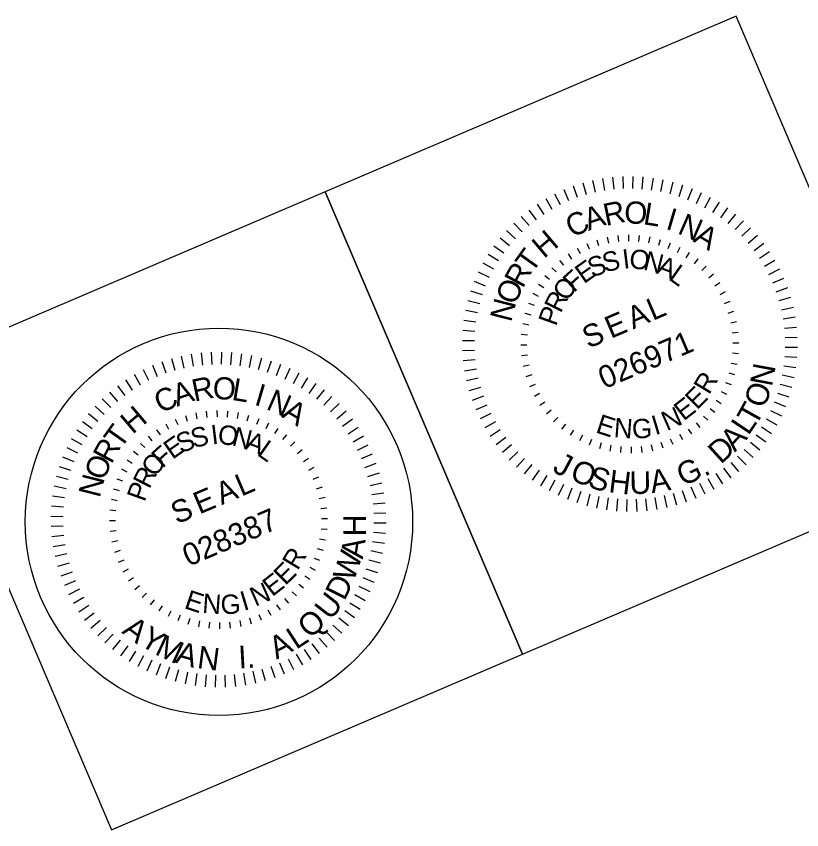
# Model space of a CAD drawing. Extents: x 1882804 to 2194450, y 87424 to 845437.
# Drawn here: x 2194137 to 2194312.8, y 87438 to 87620.1 of the extents above; entities that cross this region are included whole.
import ezdxf

# ---------------------------------------------------------------- set-up
doc = ezdxf.new("R2010")
doc.units = 0
doc.layers.add('Scratch_Level_1', color=7, linetype='Continuous')
doc.layers.add('Sheet Title CELL', color=7, linetype='Continuous')

msp = doc.modelspace()

# ---------------------------------------------------------------- linework, layer by layer
at = {"layer": 'Scratch_Level_1'}
for points in [[(2194250.33, 87477.33), (2194342.29, 87516.6), (2194298.12, 87620.06), (2194206.15, 87580.8)], [(2194158.31, 87438.05), (2194250.33, 87477.33), (2194206.15, 87580.8), (2194114.14, 87541.51)]]:
    msp.add_lwpolyline(points, close=True, dxfattribs=at)
msp.add_circle((2194182.37, 87506.94), 43.34, dxfattribs=at)
msp.add_circle((2194182.37, 87506.94), 43.34, dxfattribs=at)
at = {"layer": 'Sheet Title CELL'}
for p, q in [((2194266.67, 87580.67), (2194266.07, 87583.31)), ((2194268.73, 87581.07), (2194268.29, 87583.74)), ((2194270.81, 87581.34), (2194270.54, 87584.04)), ((2194272.91, 87581.49), (2194272.8, 87584.2)), ((2194275.01, 87581.52), (2194275.06, 87584.23)), ((2194277.11, 87581.41), (2194277.33, 87584.11)), ((2194279.2, 87581.18), (2194279.58, 87583.87)), ((2194281.27, 87580.83), (2194281.81, 87583.48)), ((2194260.67, 87578.73), (2194259.61, 87581.22)), ((2194262.63, 87579.5), (2194261.72, 87582.05)), ((2194264.63, 87580.14), (2194263.88, 87582.75)), ((2194283.32, 87580.35), (2194284.02, 87582.96)), ((2194285.33, 87579.74), (2194286.19, 87582.31)), ((2194287.3, 87579.02), (2194288.31, 87581.53)), ((2194258.77, 87577.85), (2194257.56, 87580.27)), ((2194289.23, 87578.17), (2194290.39, 87580.63)), ((2194291.1, 87577.22), (2194292.41, 87579.6)), ((2194255.13, 87575.74), (2194253.64, 87578)), ((2194256.92, 87576.85), (2194255.56, 87579.2)), ((2194292.91, 87576.15), (2194294.36, 87578.44)), ((2194253.42, 87574.53), (2194251.79, 87576.7)), ((2194294.65, 87574.98), (2194296.23, 87577.18)), ((2194296.32, 87573.7), (2194298.03, 87575.8)), ((2194251.78, 87573.22), (2194250.02, 87575.28)), ((2194297.91, 87572.32), (2194299.74, 87574.32)), ((2194248.75, 87570.3), (2194246.75, 87572.14)), ((2194250.22, 87571.81), (2194248.34, 87573.76)), ((2194299.41, 87570.85), (2194301.36, 87572.73)), ((2194247.37, 87568.72), (2194245.27, 87570.43)), ((2194269.6, 87569.28), (2194269.32, 87570.61)), ((2194271.83, 87569.64), (2194271.68, 87570.99)), ((2194274.09, 87569.77), (2194274.07, 87571.13)), ((2194276.35, 87569.69), (2194276.46, 87571.04)), ((2194278.59, 87569.38), (2194278.84, 87570.71)), ((2194300.82, 87569.29), (2194302.88, 87571.05)), ((2194246.09, 87567.05), (2194243.89, 87568.63)), ((2194265.29, 87567.93), (2194264.76, 87569.17)), ((2194267.41, 87568.71), (2194267, 87570)), ((2194280.79, 87568.85), (2194281.17, 87570.15)), ((2194282.92, 87568.12), (2194283.43, 87569.37)), ((2194302.13, 87567.66), (2194304.3, 87569.29)), ((2194244.92, 87565.31), (2194242.63, 87566.75)), ((2194261.33, 87565.75), (2194260.56, 87566.87)), ((2194263.25, 87566.94), (2194262.6, 87568.13)), ((2194284.98, 87567.17), (2194285.6, 87568.37)), ((2194286.93, 87566.03), (2194287.67, 87567.17)), ((2194303.34, 87565.94), (2194305.61, 87567.43)), ((2194259.53, 87564.39), (2194258.66, 87565.42)), ((2194288.76, 87564.7), (2194289.61, 87565.76)), ((2194304.45, 87564.15), (2194306.8, 87565.51)), ((2194243.85, 87563.5), (2194241.48, 87564.8)), ((2194257.87, 87562.85), (2194256.9, 87563.8)), ((2194290.45, 87563.2), (2194291.4, 87564.17)), ((2194305.45, 87562.3), (2194307.87, 87563.52)), ((2194242.89, 87561.63), (2194240.44, 87562.78)), ((2194256.37, 87561.16), (2194255.31, 87562.01)), ((2194291.99, 87561.54), (2194293.03, 87562.41)), ((2194306.33, 87560.39), (2194308.82, 87561.46)), ((2194242.05, 87559.7), (2194239.54, 87560.71)), ((2194255.04, 87559.33), (2194253.91, 87560.07)), ((2194293.36, 87559.74), (2194294.48, 87560.51)), ((2194241.33, 87557.72), (2194238.76, 87558.58)), ((2194253.9, 87557.37), (2194252.7, 87558)), ((2194294.54, 87557.82), (2194295.73, 87558.47)), ((2194307.1, 87558.44), (2194309.65, 87559.35)), ((2194240.73, 87555.71), (2194238.1, 87556.41)), ((2194252.95, 87555.32), (2194251.7, 87555.83)), ((2194295.53, 87555.78), (2194296.77, 87556.31)), ((2194307.74, 87556.44), (2194310.35, 87557.19)), ((2194240.24, 87553.67), (2194237.59, 87554.21)), ((2194296.31, 87553.66), (2194297.61, 87554.07)), ((2194308.27, 87554.4), (2194310.92, 87555)), ((2194252.22, 87553.19), (2194250.91, 87553.56)), ((2194308.67, 87552.34), (2194311.35, 87552.78)), ((2194239.89, 87551.6), (2194237.2, 87551.97)), ((2194251.69, 87550.98), (2194250.36, 87551.23)), ((2194296.89, 87551.47), (2194298.21, 87551.75)), ((2194308.95, 87550.26), (2194311.64, 87550.53)), ((2194239.66, 87549.51), (2194236.95, 87549.72)), ((2194251.38, 87548.74), (2194250.03, 87548.86)), ((2194297.24, 87549.24), (2194298.59, 87549.39)), ((2194239.55, 87547.41), (2194236.84, 87547.46)), ((2194297.38, 87546.98), (2194298.73, 87547)), ((2194309.1, 87548.16), (2194311.8, 87548.27)), ((2194180.83, 87542.18), (2194180.72, 87544.89)), ((2194182.93, 87542.2), (2194182.98, 87544.91)), ((2194185.03, 87542.1), (2194185.24, 87544.8)), ((2194239.58, 87545.31), (2194236.87, 87545.2)), ((2194251.3, 87546.48), (2194249.94, 87546.47)), ((2194309.12, 87546.06), (2194311.83, 87546.01)), ((2194172.55, 87540.83), (2194171.8, 87543.43)), ((2194174.59, 87541.35), (2194173.99, 87544)), ((2194176.65, 87541.75), (2194176.21, 87544.43)), ((2194178.73, 87542.03), (2194178.46, 87544.73)), ((2194187.12, 87541.87), (2194187.5, 87544.55)), ((2194189.19, 87541.51), (2194189.73, 87544.17)), ((2194191.23, 87541.03), (2194191.93, 87543.65)), ((2194193.25, 87540.43), (2194194.1, 87543)), ((2194239.73, 87543.21), (2194237.03, 87542.94)), ((2194251.43, 87544.23), (2194250.08, 87544.08)), ((2194297.29, 87544.73), (2194298.64, 87544.61)), ((2194309.02, 87543.96), (2194311.72, 87543.75)), ((2194168.59, 87539.41), (2194167.53, 87541.91)), ((2194170.55, 87540.18), (2194169.64, 87542.73)), ((2194195.22, 87539.7), (2194196.23, 87542.22)), ((2194197.15, 87538.86), (2194198.31, 87541.31)), ((2194251.79, 87541.99), (2194250.46, 87541.71)), ((2194296.98, 87542.48), (2194298.32, 87542.23)), ((2194308.79, 87541.87), (2194311.47, 87541.49)), ((2194164.84, 87537.54), (2194163.48, 87539.88)), ((2194166.69, 87538.53), (2194165.47, 87540.96)), ((2194199.02, 87537.9), (2194200.33, 87540.28)), ((2194240, 87541.13), (2194237.33, 87540.69)), ((2194252.36, 87539.81), (2194251.07, 87539.4)), ((2194296.46, 87540.29), (2194297.76, 87539.9)), ((2194308.43, 87539.8), (2194311.08, 87539.26)), ((2194163.05, 87536.43), (2194161.55, 87538.69)), ((2194200.83, 87536.84), (2194202.27, 87539.13)), ((2194202.57, 87535.66), (2194204.15, 87537.86)), ((2194240.4, 87539.06), (2194237.76, 87538.47)), ((2194253.14, 87537.69), (2194251.9, 87537.15)), ((2194295.72, 87538.15), (2194296.98, 87537.64)), ((2194307.95, 87537.76), (2194310.57, 87537.06)), ((2194159.7, 87533.9), (2194157.94, 87535.96)), ((2194161.34, 87535.22), (2194159.7, 87537.38)), ((2194204.24, 87534.38), (2194205.95, 87536.49)), ((2194240.93, 87537.03), (2194238.32, 87536.27)), ((2194294.78, 87536.09), (2194295.98, 87535.47)), ((2194307.34, 87535.74), (2194309.92, 87534.89)), ((2194158.14, 87532.49), (2194156.26, 87534.44)), ((2194205.83, 87533.01), (2194207.66, 87535)), ((2194241.58, 87535.03), (2194239.02, 87534.12)), ((2194254.13, 87535.65), (2194252.95, 87535)), ((2194293.63, 87534.14), (2194294.77, 87533.4)), ((2194156.67, 87530.99), (2194154.67, 87532.83)), ((2194207.33, 87531.54), (2194209.28, 87533.42)), ((2194242.34, 87533.07), (2194239.85, 87532.01)), ((2194255.32, 87533.72), (2194254.2, 87532.96)), ((2194292.31, 87532.31), (2194293.36, 87531.46)), ((2194306.62, 87533.77), (2194309.13, 87532.76)), ((2194155.29, 87529.4), (2194153.19, 87531.11)), ((2194175.33, 87529.4), (2194174.92, 87530.69)), ((2194177.51, 87529.97), (2194177.24, 87531.3)), ((2194179.75, 87530.32), (2194179.6, 87531.67)), ((2194182.01, 87530.46), (2194181.99, 87531.82)), ((2194184.27, 87530.37), (2194184.38, 87531.73)), ((2194186.51, 87530.07), (2194186.76, 87531.4)), ((2194188.71, 87529.54), (2194189.08, 87530.84)), ((2194208.74, 87529.98), (2194210.8, 87531.74)), ((2194243.23, 87531.17), (2194240.8, 87529.95)), ((2194256.69, 87531.92), (2194255.64, 87531.05)), ((2194258.22, 87530.27), (2194257.27, 87529.3)), ((2194290.81, 87530.62), (2194291.77, 87529.67)), ((2194305.78, 87531.85), (2194308.23, 87530.69)), ((2194154.01, 87527.73), (2194151.81, 87529.32)), ((2194171.17, 87527.62), (2194170.52, 87528.81)), ((2194173.21, 87528.61), (2194172.67, 87529.86)), ((2194190.84, 87528.8), (2194191.35, 87530.06)), ((2194192.9, 87527.86), (2194193.52, 87529.06)), ((2194210.05, 87528.34), (2194212.22, 87529.97)), ((2194244.22, 87529.32), (2194241.87, 87527.96)), ((2194259.91, 87528.77), (2194259.06, 87527.71)), ((2194289.15, 87529.08), (2194290.02, 87528.04)), ((2194304.82, 87529.97), (2194307.2, 87528.67)), ((2194152.84, 87525.99), (2194150.55, 87527.44)), ((2194169.25, 87526.44), (2194168.48, 87527.56)), ((2194194.85, 87526.72), (2194195.59, 87527.85)), ((2194211.26, 87526.62), (2194213.53, 87528.12)), ((2194245.33, 87527.53), (2194243.07, 87526.03)), ((2194261.74, 87527.44), (2194261, 87526.3)), ((2194287.34, 87527.71), (2194288.11, 87526.6)), ((2194303.75, 87528.16), (2194306.05, 87526.72)), ((2194151.77, 87524.18), (2194149.39, 87525.49)), ((2194167.45, 87525.07), (2194166.57, 87526.11)), ((2194196.68, 87525.39), (2194197.53, 87526.44)), ((2194198.37, 87523.89), (2194199.32, 87524.86)), ((2194212.37, 87524.84), (2194214.72, 87526.19)), ((2194246.54, 87525.81), (2194244.37, 87524.18)), ((2194263.7, 87526.3), (2194263.07, 87525.09)), ((2194265.75, 87525.35), (2194265.25, 87524.09)), ((2194283.38, 87525.54), (2194283.92, 87524.3)), ((2194285.42, 87526.53), (2194286.07, 87525.34)), ((2194302.58, 87526.42), (2194304.78, 87524.84)), ((2194150.81, 87522.31), (2194148.36, 87523.47)), ((2194165.79, 87523.54), (2194164.82, 87524.48)), ((2194199.91, 87522.23), (2194200.95, 87523.1)), ((2194213.37, 87522.99), (2194215.79, 87524.2)), ((2194247.85, 87524.17), (2194245.79, 87522.42)), ((2194267.89, 87524.61), (2194267.51, 87523.31)), ((2194270.09, 87524.09), (2194269.84, 87522.75)), ((2194272.33, 87523.78), (2194272.21, 87522.43)), ((2194274.59, 87523.69), (2194274.6, 87522.34)), ((2194276.84, 87523.83), (2194276.99, 87522.48)), ((2194279.08, 87524.18), (2194279.36, 87522.86)), ((2194281.26, 87524.76), (2194281.67, 87523.47)), ((2194299.93, 87523.16), (2194301.92, 87521.33)), ((2194301.3, 87524.75), (2194303.4, 87523.04)), ((2194149.97, 87520.38), (2194147.46, 87521.39)), ((2194164.29, 87521.84), (2194163.23, 87522.69)), ((2194201.28, 87520.43), (2194202.39, 87521.19)), ((2194214.25, 87521.08), (2194216.74, 87522.14)), ((2194249.27, 87522.62), (2194247.31, 87520.74)), ((2194250.77, 87521.14), (2194248.93, 87519.15)), ((2194298.45, 87521.66), (2194300.34, 87519.71)), ((2194162.96, 87520.01), (2194161.82, 87520.75)), ((2194215.02, 87519.12), (2194217.57, 87520.04)), ((2194252.35, 87519.77), (2194250.64, 87517.67)), ((2194296.9, 87520.25), (2194298.66, 87518.19)), ((2194149.25, 87518.41), (2194146.68, 87519.27)), ((2194161.82, 87518.06), (2194160.62, 87518.69)), ((2194202.46, 87518.5), (2194203.65, 87519.15)), ((2194215.66, 87517.12), (2194218.27, 87517.88)), ((2194254.02, 87518.49), (2194252.44, 87516.29)), ((2194293.54, 87517.73), (2194295.04, 87515.47)), ((2194295.26, 87518.94), (2194296.89, 87516.77)), ((2194148.64, 87516.4), (2194146.02, 87517.1)), ((2194160.87, 87516.01), (2194159.62, 87516.51)), ((2194203.45, 87516.47), (2194204.69, 87517)), ((2194216.19, 87515.09), (2194218.83, 87515.69)), ((2194255.76, 87517.32), (2194254.32, 87515.02)), ((2194257.57, 87516.25), (2194256.27, 87513.87)), ((2194291.75, 87516.62), (2194293.11, 87514.27)), ((2194148.16, 87514.35), (2194145.51, 87514.89)), ((2194160.13, 87513.87), (2194158.83, 87514.25)), ((2194204.23, 87514.35), (2194205.52, 87514.76)), ((2194259.45, 87515.29), (2194258.29, 87512.84)), ((2194261.37, 87514.45), (2194260.36, 87511.93)), ((2194286.04, 87513.97), (2194286.95, 87511.42)), ((2194288, 87514.74), (2194289.06, 87512.25)), ((2194289.9, 87515.62), (2194291.12, 87513.2)), ((2194147.81, 87512.28), (2194145.12, 87512.66)), ((2194204.81, 87512.16), (2194206.13, 87512.44)), ((2194216.59, 87513.03), (2194219.27, 87513.46)), ((2194263.34, 87513.73), (2194262.49, 87511.16)), ((2194265.36, 87513.12), (2194264.66, 87510.5)), ((2194267.4, 87512.64), (2194266.86, 87509.99)), ((2194269.48, 87512.29), (2194269.1, 87509.6)), ((2194271.57, 87512.05), (2194271.35, 87509.35)), ((2194277.86, 87512.12), (2194278.13, 87509.42)), ((2194279.94, 87512.4), (2194280.38, 87509.72)), ((2194282.01, 87512.8), (2194282.6, 87510.16)), ((2194284.04, 87513.33), (2194284.8, 87510.72)), ((2194147.58, 87510.19), (2194144.87, 87510.41)), ((2194159.61, 87511.67), (2194158.28, 87511.92)), ((2194216.87, 87510.94), (2194219.56, 87511.22)), ((2194273.66, 87511.95), (2194273.61, 87509.24)), ((2194275.76, 87511.98), (2194275.88, 87509.26)), ((2194159.3, 87509.43), (2194157.95, 87509.55)), ((2194205.16, 87509.92), (2194206.51, 87510.07)), ((2194217.02, 87508.85), (2194219.72, 87508.96)), ((2194147.47, 87508.09), (2194144.76, 87508.15)), ((2194159.21, 87507.17), (2194157.86, 87507.15)), ((2194205.3, 87507.67), (2194206.65, 87507.68)), ((2194217.04, 87506.75), (2194219.75, 87506.69)), ((2194147.5, 87505.99), (2194144.79, 87505.88)), ((2194159.35, 87504.91), (2194158, 87504.76)), ((2194205.21, 87505.41), (2194206.56, 87505.29)), ((2194147.64, 87503.89), (2194144.95, 87503.62)), ((2194204.9, 87503.17), (2194206.24, 87502.92)), ((2194216.94, 87504.65), (2194219.64, 87504.43)), ((2194147.92, 87501.81), (2194145.24, 87501.38)), ((2194159.71, 87502.68), (2194158.38, 87502.4)), ((2194216.7, 87502.56), (2194219.39, 87502.18)), ((2194148.32, 87499.75), (2194145.68, 87499.15)), ((2194160.28, 87500.49), (2194158.99, 87500.08)), ((2194204.38, 87500.97), (2194205.68, 87500.59)), ((2194216.35, 87500.49), (2194219, 87499.95)), ((2194148.85, 87497.72), (2194146.24, 87496.96)), ((2194161.06, 87498.37), (2194159.82, 87497.84)), ((2194203.64, 87498.83), (2194204.9, 87498.33)), ((2194215.87, 87498.44), (2194218.49, 87497.74)), ((2194149.5, 87495.71), (2194146.94, 87494.8)), ((2194162.05, 87496.34), (2194160.86, 87495.69)), ((2194202.69, 87496.78), (2194203.9, 87496.15)), ((2194215.26, 87496.43), (2194217.83, 87495.57)), ((2194163.24, 87494.41), (2194162.12, 87493.65)), ((2194201.55, 87494.83), (2194202.69, 87494.08)), ((2194214.54, 87494.45), (2194217.05, 87493.44)), ((2194150.26, 87493.76), (2194147.77, 87492.69)), ((2194164.6, 87492.61), (2194163.56, 87491.74)), ((2194200.22, 87493), (2194201.28, 87492.15)), ((2194213.7, 87492.53), (2194216.15, 87491.37)), ((2194151.14, 87491.85), (2194148.72, 87490.64)), ((2194166.14, 87490.95), (2194165.19, 87489.98)), ((2194198.72, 87491.3), (2194199.69, 87490.36)), ((2194212.74, 87490.66), (2194215.12, 87489.35)), ((2194152.14, 87490), (2194149.79, 87488.64)), ((2194167.83, 87489.45), (2194166.98, 87488.39)), ((2194195.26, 87488.4), (2194196.03, 87487.28)), ((2194197.06, 87489.76), (2194197.94, 87488.73)), ((2194211.67, 87488.85), (2194213.97, 87487.4)), ((2194153.25, 87488.21), (2194150.99, 87486.72)), ((2194169.66, 87488.12), (2194168.92, 87486.99)), ((2194171.61, 87486.98), (2194170.99, 87485.78)), ((2194193.34, 87487.22), (2194193.99, 87486.03)), ((2194210.5, 87487.11), (2194212.7, 87485.52)), ((2194154.46, 87486.5), (2194152.29, 87484.87)), ((2194155.77, 87484.86), (2194153.71, 87483.1)), ((2194173.67, 87486.04), (2194173.16, 87484.78)), ((2194175.81, 87485.3), (2194175.43, 87484)), ((2194178.01, 87484.77), (2194177.76, 87483.44)), ((2194187, 87484.87), (2194187.27, 87483.54)), ((2194189.18, 87485.44), (2194189.59, 87484.15)), ((2194191.3, 87486.23), (2194191.84, 87484.98)), ((2194209.22, 87485.44), (2194211.32, 87483.72)), ((2194157.19, 87483.3), (2194155.23, 87481.42)), ((2194180.25, 87484.47), (2194180.13, 87483.12)), ((2194182.51, 87484.38), (2194182.52, 87483.02)), ((2194184.76, 87484.51), (2194184.91, 87483.17)), ((2194207.84, 87483.85), (2194209.84, 87482.01)), ((2194158.69, 87481.83), (2194156.85, 87479.84)), ((2194206.37, 87482.35), (2194208.25, 87480.39)), ((2194160.27, 87480.45), (2194158.56, 87478.35)), ((2194203.18, 87479.62), (2194204.81, 87477.46)), ((2194204.82, 87480.94), (2194206.58, 87478.87)), ((2194161.94, 87479.18), (2194160.36, 87476.97)), ((2194163.68, 87478), (2194162.24, 87475.71)), ((2194201.46, 87478.41), (2194202.96, 87476.15)), ((2194165.49, 87476.93), (2194164.19, 87474.56)), ((2194167.37, 87475.98), (2194166.21, 87473.53)), ((2194197.82, 87476.31), (2194199.04, 87473.88)), ((2194199.67, 87477.3), (2194201.03, 87474.96)), ((2194169.29, 87475.14), (2194168.28, 87472.62)), ((2194171.26, 87474.41), (2194170.41, 87471.84)), ((2194191.96, 87474.01), (2194192.72, 87471.41)), ((2194193.96, 87474.66), (2194194.87, 87472.11)), ((2194195.92, 87475.42), (2194196.98, 87472.93)), ((2194173.28, 87473.81), (2194172.58, 87471.19)), ((2194175.32, 87473.33), (2194174.78, 87470.67)), ((2194177.39, 87472.97), (2194177.01, 87470.29)), ((2194179.48, 87472.74), (2194179.27, 87470.04)), ((2194181.58, 87472.64), (2194181.53, 87469.93)), ((2194183.68, 87472.66), (2194183.79, 87469.95)), ((2194185.78, 87472.81), (2194186.05, 87470.11)), ((2194187.86, 87473.08), (2194188.3, 87470.41)), ((2194189.93, 87473.49), (2194190.52, 87470.84))]:
    msp.add_line(p, q, dxfattribs=at)

# ---------------------------------------------------------------- texts
for s, height, rotation, p in [('R', 4.97, 11.906, (2194268.96, 87573.12)), ('O', 4.97, 357.7276, (2194272.99, 87573.74)), ('L', 4.97, 350.6383, (2194277.14, 87573.56)), ('C', 4.97, 26.0845, (2194261.45, 87570.41)), ('A', 4.97, 18.9953, (2194265.05, 87572.02)), ('I', 4.97, 343.5491, (2194282.14, 87572.51)), ('N', 4.97, 336.4599, (2194284.78, 87571.56)), ('H', 4.97, 40.2629, (2194255.09, 87565.72)), ('A', 4.97, 329.3706, (2194288.29, 87569.76)), ('T', 4.97, 54.4414, (2194252.41, 87562.37)), ('S', 4.34, 13.9899, (2194268.74, 87562.71)), ('I', 4.34, 6.9578, (2194272.92, 87563.54)), ('O', 4.34, 352.8935, (2194274.02, 87563.76)), ('N', 4.34, 345.8614, (2194277.15, 87563.41)), ('E', 4.34, 35.0863, (2194264.03, 87560.09)), ('S', 4.34, 21.022, (2194265.88, 87561.54)), ('A', 4.34, 338.8293, (2194280.05, 87562.59)), ('R', 4.97, 61.5306, (2194250.36, 87559)), ('F', 4.34, 42.1184, (2194261.78, 87558.1)), ('L', 4.34, 324.7651, (2194282.77, 87561.29)), ('O', 4.34, 56.1826, (2194260.32, 87556.09)), ('O', 4.97, 68.6199, (2194248.76, 87555.27)), ('R', 4.34, 63.2147, (2194258.85, 87553.45)), ('N', 4.97, 75.7091, (2194247.75, 87551.45)), ('L', 4.97, 23.1205, (2194279.45, 87551.88)), ('P', 4.34, 70.2469, (2194257.8, 87550.55)), ('E', 4.97, 23.1205, (2194270.07, 87547.87)), ('A', 4.97, 23.1205, (2194275.03, 87549.97)), ('S', 4.97, 23.1205, (2194265.02, 87545.66)), ('026971', 4.97, 23.1205, (2194268.61, 87536.59)), ('N', 5.05, 79.4552, (2194306.13, 87537.04)), ('R', 4.97, 11.906, (2194176.88, 87533.8)), ('O', 4.97, 357.7276, (2194180.91, 87534.42)), ('R', 4.34, 59.0178, (2194292.06, 87535.21)), ('A', 4.97, 18.9953, (2194172.97, 87532.7)), ('L', 4.97, 350.6383, (2194185.06, 87534.25)), ('I', 4.97, 343.5491, (2194190.06, 87533.19)), ('O', 5.05, 71.0625, (2194304.51, 87532.17)), ('C', 4.97, 26.0845, (2194169.37, 87531.09)), ('N', 4.97, 336.4599, (2194192.7, 87532.24)), ('E', 4.34, 44.9535, (2194289.33, 87531.86)), ('E', 4.34, 37.9214, (2194286.36, 87529.37)), ('T', 5.05, 60.8257, (2194302.5, 87528.15)), ('H', 4.97, 40.2629, (2194163.01, 87526.4)), ('A', 4.97, 329.3706, (2194196.21, 87530.45)), ('N', 4.34, 23.8572, (2194282.59, 87527.21)), ('E', 4.34, 341.6644, (2194266.46, 87527)), ('I', 4.34, 16.825, (2194279.99, 87526.31)), ('T', 4.97, 54.4414, (2194160.33, 87523.05)), ('I', 4.34, 6.9578, (2194180.84, 87524.23)), ('O', 4.34, 352.8935, (2194181.94, 87524.44)), ('N', 4.34, 355.7287, (2194270.63, 87525.9)), ('G', 4.34, 2.7608, (2194274.9, 87525.54)), ('L', 5.05, 56.1362, (2194300.86, 87526.1)), ('S', 4.34, 21.022, (2194173.8, 87522.22)), ('S', 4.34, 13.9899, (2194176.66, 87523.39)), ('N', 4.34, 345.8614, (2194185.07, 87524.09)), ('A', 4.34, 338.8293, (2194187.97, 87523.28)), ('A', 5.05, 47.606, (2194297.83, 87522.41)), ('R', 4.97, 61.5306, (2194158.28, 87519.69)), ('E', 4.34, 35.0863, (2194171.95, 87520.78)), ('L', 4.34, 324.7651, (2194190.69, 87521.98)), ('D', 5.05, 42.0799, (2194294.67, 87519.68)), ('F', 4.34, 42.1184, (2194169.7, 87518.79)), ('O', 4.97, 68.6199, (2194156.68, 87515.95)), ('O', 4.34, 56.1826, (2194168.24, 87516.78)), ('J', 5.05, 332.0781, (2194256.79, 87518.29)), ('O', 5.05, 337.5224, (2194260.64, 87516.49)), ('G.', 5.048, 24.7547, (2194286.24, 87514.81)), ('R', 4.34, 63.2147, (2194166.77, 87514.14)), ('L', 4.97, 23.1205, (2194187.37, 87512.56)), ('S', 5.05, 343.5688, (2194264.7, 87514.76)), ('H', 5.05, 352.9907, (2194269.42, 87513.6)), ('U', 5.05, 1.1492, (2194274.28, 87513.14)), ('A', 5.05, 9.8402, (2194279.26, 87513.33)), ('N', 4.97, 75.7091, (2194155.67, 87512.14)), ('P', 4.34, 70.2469, (2194165.72, 87511.24)), ('A', 4.97, 23.1205, (2194182.95, 87510.65)), ('E', 4.97, 23.1205, (2194177.98, 87508.55)), ('S', 4.97, 23.1205, (2194172.94, 87506.35)), ('028387', 4.97, 23.1205, (2194175.56, 87496.86)), ('H', 5.05, 89.7444, (2194215.26, 87503.68)), ('A', 5.05, 81.3518, (2194214.54, 87498.48)), ('R', 4.34, 59.0178, (2194199.98, 87495.9)), ('W', 5.05, 71.9019, (2194212.55, 87493.35)), ('E', 4.34, 44.9535, (2194197.25, 87492.54)), ('E', 4.34, 37.9214, (2194194.28, 87490.06)), ('D', 5.05, 63.5093, (2194210.44, 87489.1)), ('N', 4.34, 23.8572, (2194190.51, 87487.9)), ('E', 4.34, 341.6644, (2194174.38, 87487.68)), ('N', 4.34, 355.7287, (2194178.54, 87486.59)), ('G', 4.34, 2.7608, (2194182.82, 87486.23)), ('I', 4.34, 16.825, (2194187.91, 87486.99)), ('U', 5.05, 51.8886, (2194207.34, 87484.71)), ('Q', 5.05, 41.59, (2194202.75, 87480.62)), ('A', 5.05, 323.4723, (2194160.45, 87482.17)), ('Y', 5.05, 328.9165, (2194164.34, 87479.56)), ('L', 5.05, 33.0598, (2194199.64, 87478.26)), ('M', 5.05, 334.963, (2194167.78, 87477.4)), ('A', 5.05, 27.5337, (2194195.25, 87476.08)), ('A', 5.05, 344.3848, (2194172.37, 87475.47)), ('N', 5.05, 352.5433, (2194177.33, 87474.23)), ('I.', 5.048, 3.2047, (2194186.83, 87474.13))]:
    msp.add_text(s, height=height, rotation=rotation, dxfattribs=at).set_placement(p)

doc.saveas('drawing.dxf')
